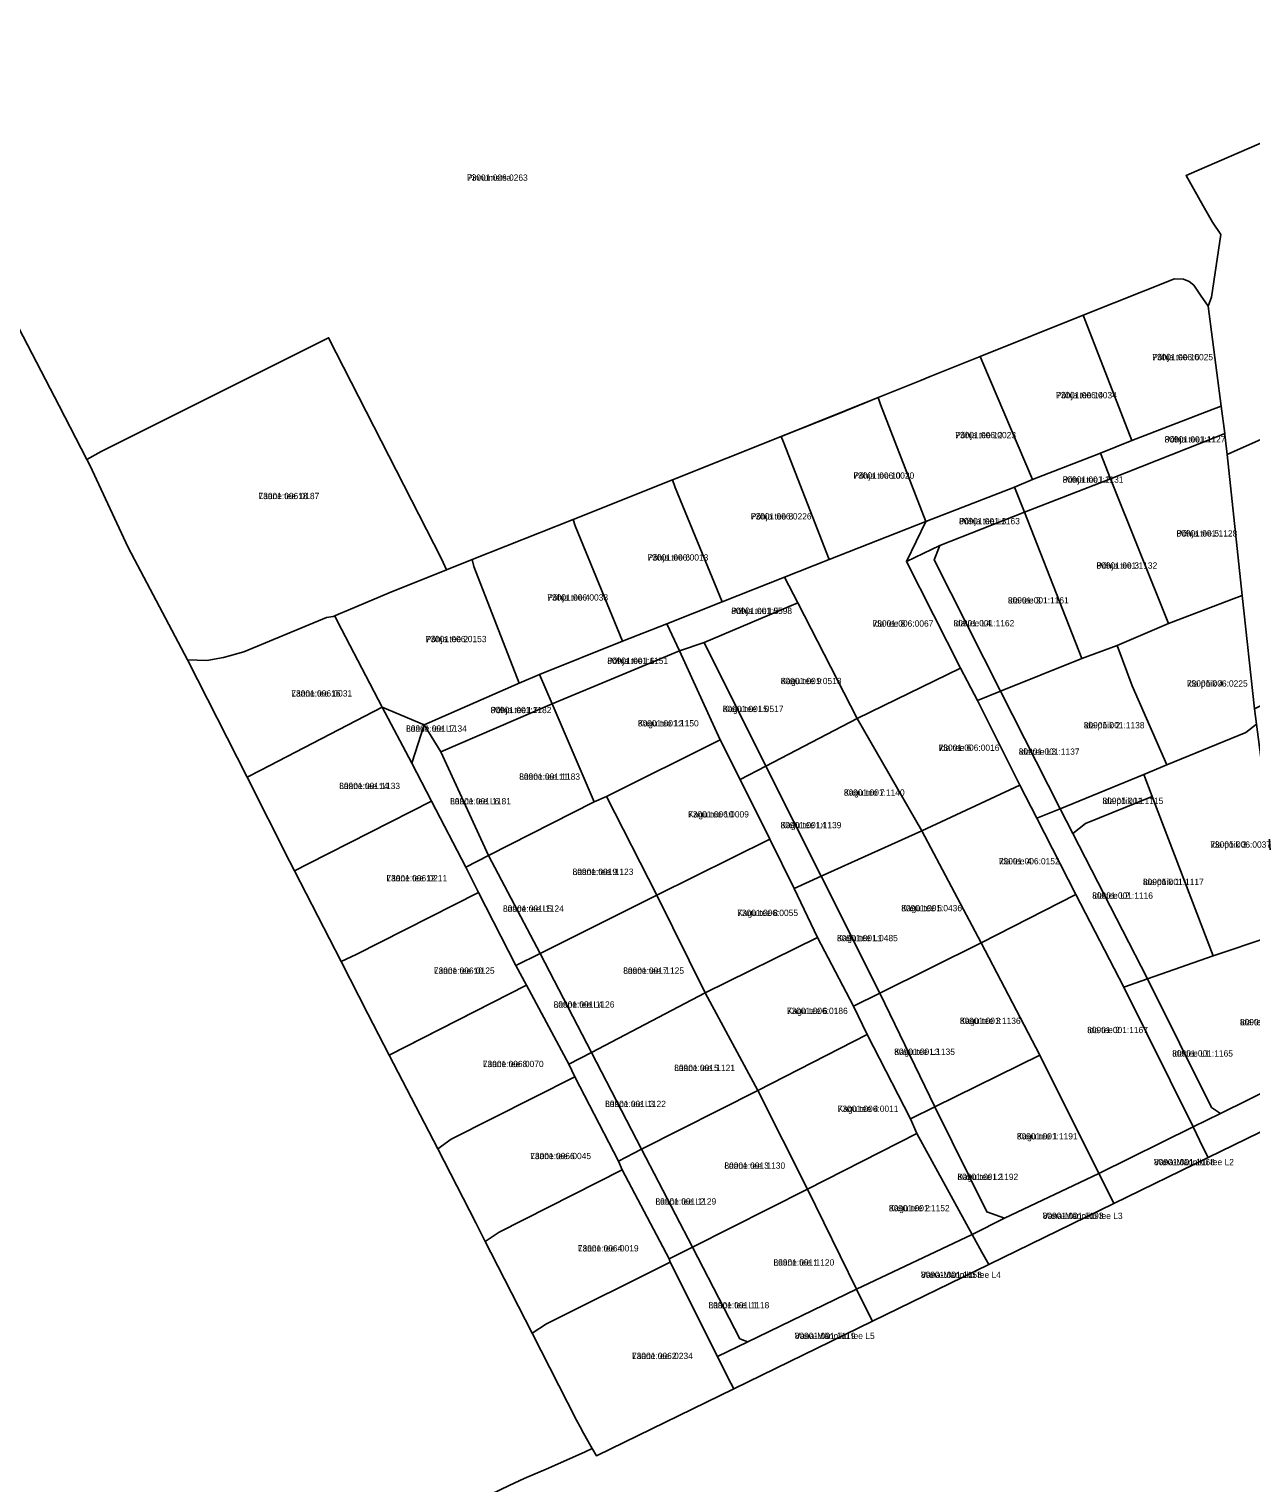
# Model space of a CAD drawing. Extents: x 524000 to 564260, y 6469338 to 6496391.
# Drawn here: x 535212.7 to 535504.2, y 6479557.1 to 6479903.9 of the extents above; entities that cross this region are included whole.
import ezdxf

# ---------------------------------------------------------------- set-up
doc = ezdxf.new("R2010")
doc.units = 0
for name, color, linetype in [('L_AADRESS', 7, 'Continuous'), ('PIIR', 7, 'Continuous'), ('TUNNUS', 7, 'Continuous')]:
    doc.layers.add(name, color=color, linetype=linetype)

msp = doc.modelspace()

# ---------------------------------------------------------------- linework, layer by layer
at = {"layer": 'PIIR'}
for points in [[(535493.99, 6479837.85), (535494.75, 6479839.93), (535497.02, 6479854.9), (535495.04, 6479857.87), (535492.82, 6479861.76), (535488.73, 6479868.98), (535491.3, 6479870.09), (535539.38, 6479890.92), (535567.95, 6479902.37), (535571.76, 6479903.9), (535599.19, 6479846.84), (535594.64, 6479845.15), (535500.96, 6479803.53), (535498.49, 6479802.43), (535497.98, 6479807.15), (535497.94, 6479807.45), (535497.1, 6479813.96)], [(535464.18, 6479835.63), (535485.91, 6479844.32), (535488.13, 6479844.22), (535489.48, 6479843.71), (535490.55, 6479842.79), (535492.17, 6479840.45), (535493.99, 6479837.84), (535497.1, 6479813.96), (535495.21, 6479813.24), (535475.75, 6479805.75), (535464.71, 6479834.27)], [(535500.96, 6479803.53), (535594.64, 6479845.15), (535599.19, 6479846.84), (535623.03, 6479798.4), (535620.21, 6479797.07), (535615.3, 6479794.75), (535583.32, 6479780.29), (535577.5, 6479777.45), (535544.52, 6479761.38), (535536.91, 6479757.58), (535505.05, 6479741.79), (535502.13, 6479768.82), (535498.49, 6479802.43)], [(535439.6, 6479825.82), (535464.18, 6479835.63), (535464.71, 6479834.27), (535475.75, 6479805.75), (535468.3, 6479802.75), (535452.06, 6479796.44), (535440.26, 6479824.31)], [(535226.5, 6479801.26), (535229.93, 6479803.14), (535284.16, 6479830.27), (535311.12, 6479777.58), (535312.31, 6479774.93), (535298.61, 6479769.47), (535290.9, 6479766.15), (535288.84, 6479765.29), (535286.52, 6479764.33), (535285.62, 6479763.96), (535285.25, 6479763.8), (535283.65, 6479763.59), (535263.94, 6479755.38), (535259.06, 6479753.98), (535255.12, 6479753.3), (535250.48, 6479753.48), (535236.38, 6479780.26), (535227.23, 6479799.86)], [(535415.83, 6479814.36), (535415.23, 6479815.99), (535425.21, 6479820.01), (535427.65, 6479821.04), (535439.6, 6479825.82), (535440.26, 6479824.31), (535452.06, 6479796.44), (535447.81, 6479794.66), (535426.59, 6479786.49)], [(535392.67, 6479805.39), (535392.12, 6479806.74), (535415.23, 6479815.99), (535415.83, 6479814.36), (535426.59, 6479786.49), (535403.56, 6479777.38)], [(535470.71, 6479796.65), (535468.3, 6479802.75), (535475.75, 6479805.75), (535495.21, 6479813.24), (535497.1, 6479813.96), (535497.94, 6479807.45), (535496.2, 6479806.76)], [(535366.82, 6479794.55), (535366.18, 6479796.4), (535392.12, 6479806.74), (535392.67, 6479805.39), (535403.56, 6479777.38), (535392.95, 6479773.2), (535378.01, 6479767.32)], [(535484.48, 6479762.12), (535470.71, 6479796.65), (535496.2, 6479806.76), (535497.94, 6479807.45), (535497.98, 6479807.15), (535498.49, 6479802.43), (535502.13, 6479768.82), (535500.15, 6479768.07)], [(535450.18, 6479788.64), (535447.81, 6479794.66), (535452.06, 6479796.44), (535468.3, 6479802.75), (535470.71, 6479796.65)], [(535343.01, 6479785.4), (535342.48, 6479786.95), (535366.18, 6479796.4), (535366.82, 6479794.55), (535378.01, 6479767.32), (535364.88, 6479762.05), (535354.24, 6479757.87)], [(535463.82, 6479753.81), (535450.18, 6479788.64), (535470.71, 6479796.65), (535484.48, 6479762.12), (535472.27, 6479756.85)], [(535422.01, 6479776.92), (535426.59, 6479786.49), (535447.81, 6479794.66), (535450.18, 6479788.64), (535429.93, 6479780.76)], [(535463.82, 6479753.81), (535444.45, 6479745.99), (535428.59, 6479777.32), (535429.93, 6479780.76), (535450.18, 6479788.64)], [(535318.8, 6479775.7), (535318.39, 6479777.35), (535342.48, 6479786.95), (535343.01, 6479785.4), (535354.24, 6479757.87), (535334.45, 6479749.93), (535329.59, 6479747.9)], [(535392.95, 6479773.2), (535403.56, 6479777.38), (535426.59, 6479786.49), (535422.01, 6479776.92), (535434.89, 6479751.45), (535410.27, 6479739.49), (535396.1, 6479767.08)], [(535434.89, 6479751.45), (535422.01, 6479776.92), (535429.93, 6479780.76), (535428.59, 6479777.32), (535444.45, 6479745.99), (535438.92, 6479743.75)], [(535286.29, 6479762.59), (535285.62, 6479763.96), (535286.52, 6479764.33), (535288.84, 6479765.29), (535290.9, 6479766.15), (535298.61, 6479769.47), (535312.31, 6479774.93), (535318.39, 6479777.35), (535318.8, 6479775.7), (535329.59, 6479747.9), (535306.97, 6479737.99), (535296.94, 6479742.13)], [(535367.85, 6479755.57), (535364.88, 6479762.05), (535378.01, 6479767.32), (535392.95, 6479773.2), (535396.1, 6479767.08), (535373.74, 6479757.62)], [(535484.14, 6479728.39), (535475.87, 6479747.23), (535472.27, 6479756.85), (535484.48, 6479762.12), (535500.15, 6479768.07), (535502.13, 6479768.82), (535505.05, 6479741.79), (535505.52, 6479738.15), (535502.93, 6479736.11)], [(535250.48, 6479753.48), (535255.12, 6479753.3), (535259.06, 6479753.98), (535263.94, 6479755.38), (535283.65, 6479763.59), (535285.25, 6479763.8), (535285.62, 6479763.96), (535286.29, 6479762.59), (535296.94, 6479742.13), (535268.01, 6479727.16), (535264.71, 6479725.45)], [(535388.49, 6479728.13), (535373.74, 6479757.62), (535396.1, 6479767.08), (535410.27, 6479739.49)], [(535337.46, 6479742.93), (535334.45, 6479749.93), (535354.24, 6479757.87), (535364.88, 6479762.05), (535367.85, 6479755.57)], [(535377.58, 6479734.39), (535367.85, 6479755.57), (535373.74, 6479757.62), (535388.49, 6479728.13), (535382.31, 6479724.92)], [(535484.14, 6479728.39), (535478.66, 6479726.09), (535458.65, 6479717.95), (535444.45, 6479745.99), (535463.82, 6479753.81), (535472.27, 6479756.85), (535475.87, 6479747.23)], [(535337.46, 6479742.93), (535367.85, 6479755.57), (535377.58, 6479734.39), (535350.47, 6479720.89), (535347.51, 6479719.58)], [(535310.95, 6479731.55), (535306.97, 6479737.99), (535329.59, 6479747.9), (535334.45, 6479749.93), (535337.46, 6479742.93)], [(535410.27, 6479739.49), (535434.89, 6479751.45), (535438.92, 6479743.75), (535449.08, 6479723.6), (535425.64, 6479712.7)], [(535322.3, 6479706.78), (535310.95, 6479731.55), (535337.46, 6479742.93), (535347.51, 6479719.58)], [(535449.08, 6479723.6), (535438.92, 6479743.75), (535444.45, 6479745.99), (535458.65, 6479717.95), (535453.12, 6479715.71)], [(535274.86, 6479705.47), (535264.71, 6479725.45), (535268.01, 6479727.16), (535296.94, 6479742.13), (535304, 6479728.83), (535308.74, 6479719.75), (535279.32, 6479704.8), (535276.06, 6479703.14)], [(535304, 6479728.83), (535296.94, 6479742.13), (535306.97, 6479737.99)], [(535425.64, 6479712.7), (535401.66, 6479701.85), (535388.49, 6479728.13), (535410.27, 6479739.49)], [(535304, 6479728.83), (535306.97, 6479737.99), (535310.95, 6479731.55), (535322.3, 6479706.78), (535316.89, 6479704.02), (535308.74, 6479719.75)], [(535484.14, 6479728.39), (535502.93, 6479736.11), (535505.52, 6479738.15), (535507.83, 6479720.37), (535509.47, 6479698.85), (535510.31, 6479687.98), (535508.42, 6479687.34), (535495.17, 6479682.86), (535480.64, 6479720.89), (535478.66, 6479726.09)], [(535350.47, 6479720.89), (535377.58, 6479734.39), (535382.31, 6479724.92), (535389.39, 6479710.66), (535362.44, 6479697.33)], [(535389.39, 6479710.66), (535382.31, 6479724.92), (535388.49, 6479728.13), (535401.66, 6479701.85), (535395.2, 6479698.93)], [(535461.67, 6479712.04), (535458.65, 6479717.95), (535478.66, 6479726.09), (535480.64, 6479720.89), (535464.68, 6479714.43)], [(535425.64, 6479712.7), (535449.08, 6479723.6), (535453.12, 6479715.71), (535462.45, 6479697.45), (535439.86, 6479685.96)], [(535287.14, 6479681.52), (535276.06, 6479703.14), (535279.32, 6479704.8), (535308.74, 6479719.75), (535316.89, 6479704.02), (535319.88, 6479697.98), (535290.74, 6479683.17)], [(535362.44, 6479697.33), (535334.63, 6479683.44), (535322.3, 6479706.78), (535347.51, 6479719.58), (535350.47, 6479720.89)], [(535479.51, 6479677.34), (535461.67, 6479712.04), (535464.68, 6479714.43), (535480.64, 6479720.89), (535495.17, 6479682.86)], [(535462.45, 6479697.45), (535453.12, 6479715.71), (535458.65, 6479717.95), (535461.67, 6479712.04), (535479.51, 6479677.34), (535473.88, 6479675.37)], [(535401.66, 6479701.85), (535425.64, 6479712.7), (535439.86, 6479685.96), (535415.67, 6479673.97)], [(535362.44, 6479697.33), (535389.39, 6479710.66), (535395.2, 6479698.93), (535400.81, 6479687.22), (535373.99, 6479674.05)], [(535319.88, 6479697.98), (535316.89, 6479704.02), (535322.3, 6479706.78), (535334.63, 6479683.44), (535328.82, 6479680.53)], [(535401.66, 6479701.85), (535415.67, 6479673.97), (535409.36, 6479670.84), (535400.81, 6479687.22), (535395.2, 6479698.93)], [(535287.14, 6479681.52), (535290.74, 6479683.17), (535319.88, 6479697.98), (535328.82, 6479680.53), (535331.36, 6479675.85), (535298.62, 6479659.19), (535293.55, 6479669)], [(535373.99, 6479674.05), (535346.85, 6479659.84), (535334.63, 6479683.44), (535362.44, 6479697.33)], [(535439.86, 6479685.96), (535462.45, 6479697.45), (535473.88, 6479675.37), (535490.37, 6479642.06), (535467.9, 6479630.98), (535453.81, 6479659.14)], [(535523.61, 6479658.45), (535496.9, 6479645.28), (535494.79, 6479646.71), (535479.51, 6479677.34), (535495.17, 6479682.86), (535508.42, 6479687.34), (535519.5, 6479666.31), (535522.27, 6479660.97)], [(535373.99, 6479674.05), (535400.81, 6479687.22), (535409.36, 6479670.84), (535412.62, 6479664.11), (535386.54, 6479650.73)], [(535453.81, 6479659.14), (535428.79, 6479646.87), (535415.67, 6479673.97), (535439.86, 6479685.96)], [(535331.36, 6479675.85), (535328.82, 6479680.53), (535334.63, 6479683.44), (535346.85, 6479659.84), (535341.45, 6479657.03)], [(535490.37, 6479642.06), (535473.88, 6479675.37), (535479.51, 6479677.34), (535494.79, 6479646.71), (535496.9, 6479645.28)], [(535310.18, 6479636.79), (535298.62, 6479659.19), (535302.32, 6479661.1), (535331.36, 6479675.85), (535341.45, 6479657.03), (535342.92, 6479653.98), (535313.37, 6479639.14)], [(535386.54, 6479650.73), (535358.8, 6479636.71), (535346.85, 6479659.84), (535373.99, 6479674.05)], [(535412.62, 6479664.11), (535409.36, 6479670.84), (535415.67, 6479673.97), (535428.79, 6479646.87), (535422.95, 6479643.99)], [(535386.54, 6479650.73), (535412.62, 6479664.11), (535422.95, 6479643.99), (535424.47, 6479640.5), (535398.38, 6479627.17)], [(535342.92, 6479653.98), (535341.45, 6479657.03), (535346.85, 6479659.84), (535358.8, 6479636.71), (535353.32, 6479633.92)], [(535467.9, 6479630.98), (535445.37, 6479620.27), (535441.15, 6479621.76), (535428.79, 6479646.87), (535453.81, 6479659.14)], [(535492.74, 6479637.26), (535490.37, 6479642.06), (535496.9, 6479645.28), (535523.61, 6479658.45), (535526.24, 6479653.42), (535527.47, 6479651.06), (535493.99, 6479634.74)], [(535321.54, 6479614.75), (535319.28, 6479619.19), (535310.18, 6479636.79), (535313.37, 6479639.14), (535342.92, 6479653.98), (535353.32, 6479633.92), (535354.17, 6479631.85), (535324.84, 6479616.92)], [(535398.38, 6479627.17), (535370.94, 6479613.41), (535358.8, 6479636.71), (535386.54, 6479650.73)], [(535424.47, 6479640.5), (535422.95, 6479643.99), (535428.79, 6479646.87), (535441.15, 6479621.76), (535445.37, 6479620.27), (535437.7, 6479616.38)], [(535398.38, 6479627.17), (535424.47, 6479640.5), (535437.7, 6479616.38), (535410.11, 6479603.35)], [(535470.28, 6479626.23), (535467.9, 6479630.98), (535490.37, 6479642.06), (535492.74, 6479637.26), (535493.99, 6479634.74), (535471.51, 6479623.78)], [(535354.17, 6479631.85), (535353.32, 6479633.92), (535358.8, 6479636.71), (535370.94, 6479613.41), (535365.38, 6479610.58)], [(535332.71, 6479592.84), (535322.89, 6479612.1), (535321.54, 6479614.75), (535324.84, 6479616.92), (535354.17, 6479631.85), (535365.38, 6479610.58), (535365.61, 6479609.77), (535336.14, 6479595.05)], [(535440, 6479612.21), (535437.7, 6479616.38), (535445.37, 6479620.27), (535467.9, 6479630.98), (535470.28, 6479626.23), (535471.51, 6479623.78), (535441.64, 6479609.22)], [(535410.11, 6479603.35), (535384.17, 6479590.81), (535382.26, 6479591.52), (535370.94, 6479613.41), (535398.38, 6479627.17)], [(535412.56, 6479598.38), (535410.11, 6479603.35), (535437.7, 6479616.38), (535440, 6479612.21), (535441.64, 6479609.22), (535413.89, 6479595.7)], [(535365.61, 6479609.77), (535365.38, 6479610.58), (535370.94, 6479613.41), (535382.26, 6479591.52), (535384.17, 6479590.81), (535376.92, 6479587.32)], [(535347.04, 6479565.36), (535346.75, 6479565.88), (535344.98, 6479569.02), (535344.15, 6479570.53), (535343.27, 6479572.12), (535332.71, 6479592.84), (535336.14, 6479595.05), (535365.61, 6479609.77), (535376.92, 6479587.32), (535379.43, 6479582.32), (535380.8, 6479579.57), (535348.03, 6479563.61)], [(535379.43, 6479582.32), (535376.92, 6479587.32), (535384.17, 6479590.81), (535410.11, 6479603.35), (535412.56, 6479598.38), (535413.89, 6479595.7), (535380.8, 6479579.57)]]:
    msp.add_lwpolyline(points, close=True, dxfattribs=at)
for points in [[(535539.38, 6479890.92), (535491.3, 6479870.09), (535488.73, 6479868.98), (535492.82, 6479861.76), (535495.04, 6479857.87), (535497.02, 6479854.9), (535494.75, 6479839.93), (535493.99, 6479837.84), (535492.17, 6479840.45), (535490.55, 6479842.79), (535489.48, 6479843.71), (535488.13, 6479844.22), (535485.91, 6479844.32), (535464.18, 6479835.63), (535439.6, 6479825.82), (535427.65, 6479821.04), (535425.21, 6479820.01), (535415.23, 6479815.99), (535405.56, 6479812.09), (535392.12, 6479806.74), (535366.18, 6479796.4), (535342.48, 6479786.95), (535318.39, 6479777.35), (535312.31, 6479774.93), (535311.12, 6479777.58), (535284.16, 6479830.27), (535229.93, 6479803.14), (535226.5, 6479801.26), (535219.86, 6479814.06), (535192.83, 6479865.96)], [(535192.83, 6479865.96), (535219.86, 6479814.06), (535226.5, 6479801.26), (535227.23, 6479799.86), (535236.38, 6479780.26), (535250.48, 6479753.48), (535264.71, 6479725.45), (535274.86, 6479705.47), (535276.06, 6479703.14), (535287.14, 6479681.52), (535293.55, 6479669), (535298.62, 6479659.19), (535310.18, 6479636.79), (535319.28, 6479619.19), (535321.54, 6479614.75), (535322.89, 6479612.1), (535332.71, 6479592.84), (535343.27, 6479572.12), (535344.15, 6479570.53), (535344.98, 6479569.02), (535346.75, 6479565.88), (535347.04, 6479565.36), (535345.33, 6479564.59), (535336.64, 6479560.66), (535330.8, 6479558.19), (535327.22, 6479556.53)], [(535175.96, 6479483.05), (535239.53, 6479514.01), (535291.23, 6479539.21), (535327.22, 6479556.53), (535330.8, 6479558.19), (535336.64, 6479560.66), (535345.33, 6479564.59), (535347.04, 6479565.36), (535348.03, 6479563.61), (535380.8, 6479579.57), (535413.89, 6479595.7), (535441.64, 6479609.22), (535471.51, 6479623.78), (535493.99, 6479634.74), (535527.47, 6479651.06), (535616.07, 6479694.24), (535628.34, 6479700.45), (535639.26, 6479705.93), (535642.49, 6479707.04), (535645.03, 6479707.51), (535662.18, 6479715.6), (535803, 6479425.99)]]:
    msp.add_lwpolyline(points, dxfattribs=at)

# ---------------------------------------------------------------- texts
at = {"layer": 'L_AADRESS'}
for s, p in [('Pinnumetsa', (535317.16, 6479867.72)), ('Põhja tee 16', (535480.64, 6479824.92)), ('Põhja tee 14', (535457.68, 6479815.83)), ('Põhja tee 12', (535433.64, 6479806.32)), ('Põhja tee L1', (535483.59, 6479805.3)), ('Põhja tee 10', (535409.36, 6479796.66)), ('Põhja tee L2', (535459.27, 6479795.7)), ('Lääne tee 18', (535267.43, 6479791.79)), ('Põhja tee 8', (535384.87, 6479786.93)), ('Põhja tee L3', (535434.56, 6479785.79)), ('Põhja tee 5', (535486.42, 6479782.87)), ('Põhja tee 6', (535360.24, 6479777.13)), ('Põhja tee 3', (535467.33, 6479775.2)), ('Põhja tee 4', (535336.32, 6479767.59)), ('Ida tee 3', (535446.21, 6479766.9)), ('Põhja tee L5', (535380.21, 6479764.38)), ('Ida tee 8', (535413.92, 6479761.37)), ('Ida tee L4', (535433.23, 6479761.44)), ('Põhja tee 2', (535307.32, 6479757.67)), ('Põhja tee L6', (535350.64, 6479752.49)), ('Kagu tee 9', (535392.01, 6479747.66)), ('Ida põik 4', (535488.9, 6479747.07)), ('Lääne tee 16', (535275.27, 6479744.71)), ('Põhja tee L7', (535322.8, 6479740.74)), ('Kagu tee L5', (535378.17, 6479740.99)), ('Lääne tee L7', (535302.64, 6479736.32)), ('Kagu tee 12', (535357.94, 6479737.57)), ('Ida põik 2', (535464.3, 6479737.11)), ('Ida tee 6', (535429.68, 6479731.75)), ('Ida tee L3', (535448.79, 6479730.81)), ('Lääne tee 11', (535329.63, 6479724.86)), ('Lääne tee 14', (535286.69, 6479722.63)), ('Kagu tee 7', (535407.07, 6479721.06)), ('Lääne tee L6', (535313.15, 6479718.99)), ('Ida põik L1', (535468.76, 6479719.07)), ('Kagu tee 10', (535369.92, 6479715.86)), ('Kagu tee L4', (535391.98, 6479713.29)), ('Ida põik 3', (535494.48, 6479708.65)), ('Ida tee 4', (535444.05, 6479704.67)), ('Lääne tee 12', (535297.95, 6479700.63)), ('Lääne tee 9', (535342.36, 6479702.17)), ('Ida põik 1', (535478.42, 6479699.73)), ('Ida tee L2', (535466.31, 6479696.49)), ('Lääne tee L5', (535325.76, 6479693.37)), ('Kagu tee 5', (535420.76, 6479693.49)), ('Kagu tee 8', (535381.63, 6479692.36)), ('Kagu tee L1', (535405.44, 6479686.35)), ('Lääne tee 10', (535309.26, 6479678.58)), ('Lääne tee 7', (535354.44, 6479678.58)), ('Lääne tee L4', (535337.84, 6479670.51)), ('Kagu tee 6', (535393.49, 6479668.98)), ('Kagu tee 3', (535434.74, 6479666.61)), ('Ida tee 1', (535501.56, 6479666.3)), ('Ida tee 2', (535465.11, 6479664.42)), ('Kagu tee L3', (535419.07, 6479659.24)), ('Ida tee L1', (535485.39, 6479658.84)), ('Lääne tee 8', (535320.95, 6479656.32)), ('Lääne tee 5', (535366.6, 6479655.38)), ('Lääne tee L3', (535350.12, 6479646.79)), ('Kagu tee 4', (535405.6, 6479645.64)), ('Kagu tee 1', (535448.34, 6479639.07)), ('Lääne tee 6', (535332.26, 6479634.37)), ('Lääne tee 3', (535378.57, 6479632.07)), ('Vana-Männiku tee L2', (535481.05, 6479632.92)), ('Kagu tee L2', (535434.16, 6479629.4)), ('Lääne tee L2', (535362.13, 6479623.53)), ('Kagu tee 2', (535417.81, 6479621.93)), ('Vana-Männiku tee L3', (535454.5, 6479620.1)), ('Lääne tee 4', (535343.61, 6479612.35)), ('Lääne tee 1', (535390.28, 6479608.99)), ('Vana-Männiku tee L4', (535425.46, 6479606.04)), ('Lääne tee L1', (535374.78, 6479598.79)), ('Vana-Männiku tee L5', (535395.35, 6479591.46)), ('Lääne tee 2', (535356.54, 6479586.69))]:
    msp.add_text(s, height=1.5, dxfattribs=at).set_placement(p)
at = {"layer": 'TUNNUS'}
for s, p in [('73001:006:0263', (535317.16, 6479867.72)), ('73001:006:0025', (535480.64, 6479824.92)), ('73001:006:0034', (535457.68, 6479815.83)), ('73001:006:0023', (535433.64, 6479806.32)), ('80901:001:1127', (535483.59, 6479805.3)), ('73001:006:0020', (535409.36, 6479796.66)), ('80901:001:1131', (535459.27, 6479795.7)), ('73001:006:0187', (535267.43, 6479791.79)), ('73001:006:0226', (535384.87, 6479786.93)), ('80901:001:1163', (535434.56, 6479785.79)), ('80901:001:1128', (535486.42, 6479782.87)), ('73001:006:0013', (535360.24, 6479777.13)), ('80901:001:1132', (535467.33, 6479775.2)), ('73001:006:0038', (535336.32, 6479767.59)), ('80901:001:1161', (535446.21, 6479766.9)), ('80901:001:0598', (535380.21, 6479764.38)), ('73001:006:0067', (535413.92, 6479761.37)), ('80901:001:1162', (535433.23, 6479761.44)), ('73001:006:0153', (535307.32, 6479757.67)), ('80901:001:1151', (535350.64, 6479752.49)), ('80901:001:0518', (535392.01, 6479747.66)), ('73001:006:0225', (535488.9, 6479747.07)), ('73001:006:0031', (535275.27, 6479744.71)), ('80901:001:1182', (535322.8, 6479740.74)), ('80901:001:0517', (535378.17, 6479740.99)), ('80901:001:1134', (535302.64, 6479736.32)), ('80901:001:1150', (535357.94, 6479737.57)), ('80901:001:1138', (535464.3, 6479737.11)), ('73001:006:0016', (535429.68, 6479731.75)), ('80901:001:1137', (535448.79, 6479730.81)), ('80901:001:1183', (535329.63, 6479724.86)), ('80901:001:1133', (535286.69, 6479722.63)), ('80901:001:1140', (535407.07, 6479721.06)), ('80901:001:1181', (535313.15, 6479718.99)), ('80901:001:1115', (535468.76, 6479719.07)), ('73001:006:0009', (535369.92, 6479715.86)), ('80901:001:1139', (535391.98, 6479713.29)), ('73001:006:0037', (535494.48, 6479708.65)), ('73001:006:0152', (535444.05, 6479704.67)), ('73001:006:0211', (535297.95, 6479700.63)), ('80901:001:1123', (535342.36, 6479702.17)), ('80901:001:1117', (535478.42, 6479699.73)), ('80901:001:1116', (535466.31, 6479696.49)), ('80901:001:1124', (535325.76, 6479693.37)), ('80901:001:0436', (535420.76, 6479693.49)), ('73001:006:0055', (535381.63, 6479692.36)), ('80901:001:0485', (535405.44, 6479686.35)), ('73001:006:0125', (535309.26, 6479678.58)), ('80901:001:1125', (535354.44, 6479678.58)), ('80901:001:1126', (535337.84, 6479670.51)), ('73001:006:0186', (535393.49, 6479668.98)), ('80901:001:1136', (535434.74, 6479666.61)), ('80901:001:1164', (535501.56, 6479666.3)), ('80901:001:1167', (535465.11, 6479664.42)), ('80901:001:1135', (535419.07, 6479659.24)), ('80901:001:1165', (535485.39, 6479658.84)), ('73001:006:0070', (535320.95, 6479656.32)), ('80901:001:1121', (535366.6, 6479655.38)), ('80901:001:1122', (535350.12, 6479646.79)), ('73001:006:0011', (535405.6, 6479645.64)), ('80901:001:1191', (535448.34, 6479639.07)), ('73001:006:0045', (535332.26, 6479634.37)), ('80901:001:1130', (535378.57, 6479632.07)), ('80901:001:1168', (535481.05, 6479632.92)), ('80901:001:1192', (535434.16, 6479629.4)), ('80901:001:1129', (535362.13, 6479623.53)), ('80901:001:1152', (535417.81, 6479621.93)), ('80901:001:1193', (535454.5, 6479620.1)), ('73001:006:0019', (535343.61, 6479612.35)), ('80901:001:1120', (535390.28, 6479608.99)), ('80901:001:1153', (535425.46, 6479606.04)), ('80901:001:1118', (535374.78, 6479598.79)), ('80901:001:1119', (535395.35, 6479591.46)), ('73001:006:0234', (535356.54, 6479586.69))]:
    msp.add_text(s, height=1.5, dxfattribs=at).set_placement(p)

doc.saveas('drawing.dxf')
